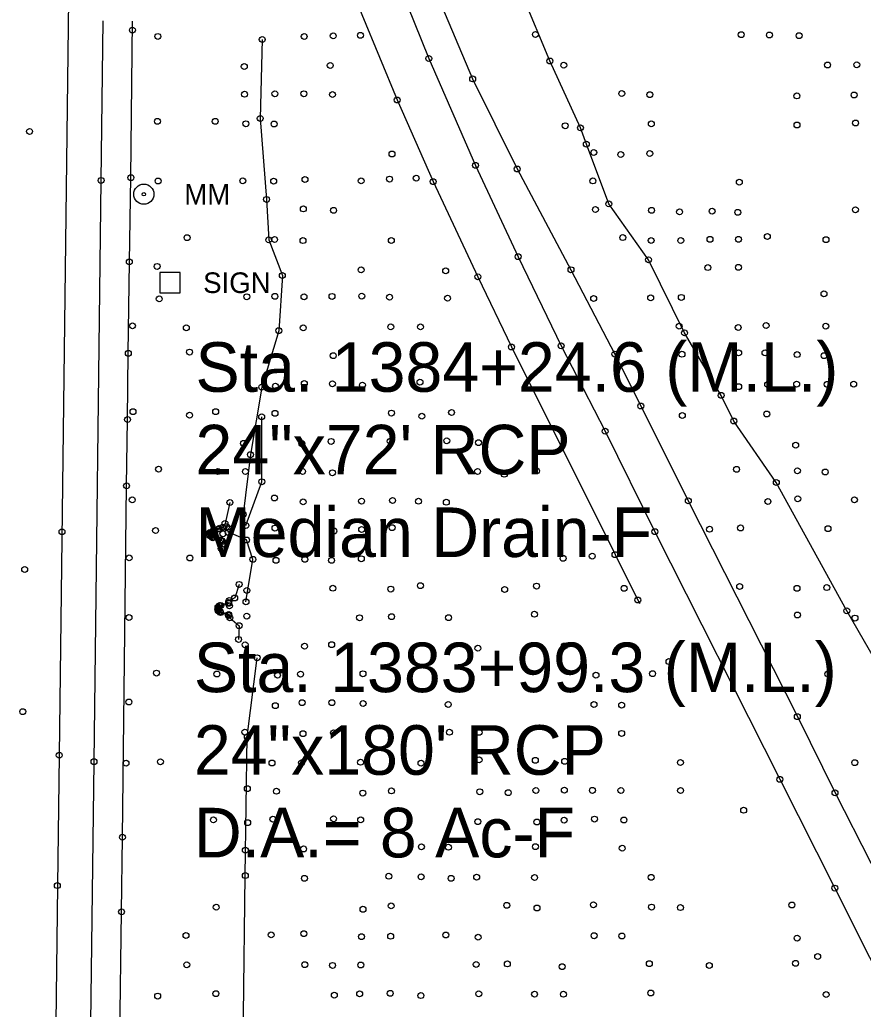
# Model space of a CAD drawing. Extents: x 20503438 to 20508873, y 7964251 to 7984667.
# Drawn here: x 20506709.7 to 20506995.6, y 7971063.7 to 7971399 of the extents above; entities that cross this region are included whole.
import ezdxf

# ---------------------------------------------------------------- set-up
doc = ezdxf.new("R2010")
doc.units = 0
for name, color, linetype in [('SurBreakLine', 7, 'Continuous'), ('SurConcreteSlab', 7, 'Continuous'), ('SurDrainageArrowDown', 7, 'Continuous'), ('SurDrainageArrowUp', 7, 'Continuous'), ('SurEdgeRoadPaved', 7, 'Continuous'), ('SurEdgeShoulderPaved', 7, 'Continuous'), ('SurPointsNonDTM', 7, 'Continuous'), ('SurRoadPoints', 7, 'Continuous'), ('SurSurveyPoints', 7, 'Continuous'), ('SurTxtDrainage', 7, 'Continuous')]:
    doc.layers.add(name, color=color, linetype=linetype)

msp = doc.modelspace()

# ---------------------------------------------------------------- linework, layer by layer
at = {"layer": 'SurBreakLine'}
for points in [[(20506748.06, 7973121.35), (20506742.68, 7972730.78), (20506738.51, 7972374.69), (20506737.86, 7972337.8), (20506736.71, 7972242.37), (20506735.23, 7972125.23), (20506734.95, 7972091.62), (20506733.69, 7971999.07), (20506733.06, 7971941.23), (20506731.39, 7971811.28), (20506730.1, 7971695.4), (20506729.05, 7971627.9), (20506728.3, 7971561.44), (20506726.5, 7971429.38), (20506726.18, 7971406.05), (20506723.05, 7971149.78), (20506722.41, 7971105.59), (20506719.46, 7970853.94), (20506718.67, 7970817.35), (20506718.46, 7970790.57), (20506717.85, 7970756.37), (20506717.5, 7970726.21), (20506716.72, 7970686.1), (20506716.2, 7970609.97)], [(20506780.89, 7971235.43), (20506779.24, 7971228.33), (20506778.42, 7971227.05), (20506775.45, 7971226.15), (20506774.06, 7971225.2), (20506774.11, 7971224.15), (20506775.06, 7971223.48), (20506778.01, 7971222.5), (20506778.4, 7971222.21), (20506777.97, 7971219.86)], [(20506784.01, 7971207.67), (20506782.52, 7971203.07), (20506780.66, 7971202.2)], [(20506780.57, 7971197.26), (20506780.88, 7971196.35), (20506784, 7971193.68), (20506783.83, 7971189.03)]]:
    msp.add_lwpolyline(points, dxfattribs=at)
at = {"layer": 'SurConcreteSlab'}
msp.add_lwpolyline([(20506833.63, 7971422.4), (20506848.3, 7971385.94), (20506864.15, 7971349.7), (20506878.6, 7971318.75), (20506893.18, 7971288.54), (20506908.07, 7971259.59), (20506924.96, 7971225.54), (20506967.3, 7971141.62), (20506985.94, 7971104.75), (20506997.76, 7971081.32), (20507017.18, 7971042.95), (20507056.79, 7970964.03), (20507084.68, 7970908.59), (20507110.53, 7970856.92), (20507136.29, 7970805.35), (20507160.76, 7970756.88), (20507196.93, 7970685.17), (20507205.99, 7970667.01), (20507228.8, 7970620.83), (20507263.82, 7970554.5)], dxfattribs=at)
for points in [[(20506778.13, 7971222.53), (20506775.12, 7971223.72), (20506774.58, 7971224.33), (20506774.56, 7971225.28), (20506775.09, 7971225.84), (20506777.19, 7971226.63), (20506778.42, 7971226.96), (20506777.25, 7971226.37), (20506775.14, 7971225.72), (20506774.71, 7971224.99), (20506774.85, 7971224.22), (20506775.53, 7971223.68), (20506777.73, 7971222.73)], [(20506780.47, 7971201.27), (20506777.83, 7971200.52), (20506776.99, 7971199.91), (20506776.95, 7971199.07), (20506777.53, 7971198.46), (20506780.49, 7971197.48), (20506780.43, 7971197.16), (20506777.73, 7971198.12), (20506776.9, 7971198.75), (20506776.8, 7971199.27), (20506776.86, 7971199.89), (20506777.41, 7971200.52), (20506780.47, 7971201.58)]]:
    msp.add_lwpolyline(points, close=True, dxfattribs=at)
at = {"layer": 'SurDrainageArrowDown'}
for points in [[(20507224.7, 7970759.18), (20507204.45, 7970804.1), (20507184.9, 7970841.74), (20507169.23, 7970884.93), (20507146.3, 7970924.33), (20507137.63, 7970936.09), (20507135.68, 7970938.54), (20507132.89, 7970943.61), (20507112.81, 7970984), (20507088.76, 7971026.9), (20507065.73, 7971065.56), (20507040.06, 7971109.35), (20507016.49, 7971152.89), (20506989.99, 7971198.73), (20506966.12, 7971242.22), (20506951.68, 7971263.05), (20506947.42, 7971271.75), (20506935.02, 7971292.93), (20506922.81, 7971317.7), (20506909.33, 7971336.65), (20506901.73, 7971356.91), (20506899.73, 7971362.43), (20506889.38, 7971385.08), (20506880.22, 7971407.2)], [(20506791.87, 7971392.37), (20506791.18, 7971365.61), (20506793.32, 7971338.17), (20506794.07, 7971324.45), (20506798.67, 7971312.37), (20506797.47, 7971293.67), (20506791.69, 7971274.55), (20506787.85, 7971251.66), (20506785.4, 7971231.45)], [(20506758.23, 7970612.66), (20506759.96, 7970618.07), (20506766.03, 7970640.28), (20506769.58, 7970650.69), (20506772.91, 7970661.98), (20506773.11, 7970678.32), (20506770.25, 7970703.37), (20506769.67, 7970724.66), (20506772.21, 7970747.11), (20506774.83, 7970769.77), (20506774.2, 7970791.54), (20506775.89, 7970837.25), (20506778.93, 7970889.1), (20506783.31, 7970939.45), (20506783.6, 7970964.79), (20506784.75, 7971014.54), (20506785.47, 7971061.82), (20506786.12, 7971108.98), (20506786.8, 7971156.01), (20506790.11, 7971182.82)]]:
    msp.add_lwpolyline(points, dxfattribs=at)
at = {"layer": 'SurDrainageArrowUp'}
for points in [[(20506786.33, 7971227.62), (20506791.69, 7971242.47), (20506791.67, 7971264.48)], [(20506786.34, 7971201.77), (20506788.69, 7971216.16), (20506786.54, 7971222.74), (20506780.31, 7971225.34)]]:
    msp.add_lwpolyline(points, dxfattribs=at)
at = {"layer": 'SurEdgeRoadPaved'}
for points in [[(20506743.39, 7971800.54), (20506747.79, 7971744.03), (20506751.01, 7971706.87), (20506755, 7971665.38), (20506760.15, 7971636.1), (20506765.16, 7971607.46), (20506771.8, 7971576.17), (20506779.74, 7971543.31), (20506787.73, 7971513.32), (20506796.06, 7971484.28), (20506807.04, 7971451.34), (20506815.03, 7971428.73), (20506825.58, 7971400.86), (20506837.6, 7971371.87), (20506849.8, 7971344.18), (20506864.95, 7971311.94), (20506876.32, 7971288.15), (20506911.44, 7971217.76), (20506919.79, 7971201.17)], [(20506851.33, 7971406.99), (20506863.18, 7971379), (20506878.28, 7971348.48), (20506896.51, 7971314.33), (20506911.4, 7971285.72), (20506920.16, 7971268.15), (20506936.29, 7971235.99), (20506973.25, 7971162.85), (20506986.02, 7971137.03), (20506998.15, 7971113.28), (20507008.91, 7971092.3), (20507021.67, 7971066.98), (20507054.15, 7971002), (20507084.27, 7970942.48), (20507118.86, 7970873.87), (20507143.37, 7970824.92), (20507173.68, 7970764.24), (20507214.03, 7970684.3), (20507241.61, 7970629.82), (20507252.24, 7970614.59), (20507261.23, 7970604), (20507267.87, 7970598.31), (20507278.37, 7970591.06), (20507287.18, 7970585.98)], [(20506728.28, 7970614.49), (20506729.78, 7970744.63), (20506731.29, 7970864.38), (20506734.84, 7971147.58), (20506737.24, 7971344.61), (20506737.94, 7971398.74)]]:
    msp.add_lwpolyline(points, dxfattribs=at)
at = {"layer": 'SurEdgeShoulderPaved'}
msp.add_lwpolyline([(20506738.37, 7970630.83), (20506738.67, 7970664.94), (20506740.63, 7970809.56), (20506741.32, 7970878.14), (20506742.07, 7970919.76), (20506742.54, 7970949.49), (20506742.91, 7970990.73), (20506743.22, 7971026.05), (20506743.58, 7971054.27), (20506744.17, 7971096.69), (20506744.47, 7971121.99), (20506745.87, 7971241.09), (20506746.19, 7971263.55), (20506746.45, 7971286), (20506746.82, 7971317), (20506747.35, 7971345.54), (20506747.87, 7971398.62)], dxfattribs=at)
at = {"layer": 'SurPointsNonDTM'}
msp.add_circle((20506723.97, 7971225.51), 1, dxfattribs=at)
at = {"layer": 'SurRoadPoints'}
msp.add_lwpolyline([(20506760.62, 7971306.5), (20506760.62, 7971306.5), (20506764.05, 7971306.5), (20506764.05, 7971313.36), (20506757.19, 7971313.36), (20506757.19, 7971306.5), (20506760.62, 7971306.5)], dxfattribs=at)
for radius in [3.43, 0.571]:
    msp.add_circle((20506751.72, 7971339.93), radius, dxfattribs=at)
at = {"layer": 'SurSurveyPoints'}
for centre in [(20506747.84, 7971395.54), (20506756.47, 7971393.42), (20506791.87, 7971392.37), (20506806.08, 7971393.38), (20506815.91, 7971393.6), (20506825.14, 7971393.78), (20506884.45, 7971394.08), (20506954.23, 7971393.99), (20506963.77, 7971393.89), (20506973.84, 7971393.66), (20506848.3, 7971385.94), (20506785.77, 7971383.19), (20506814.92, 7971383.56), (20506889.38, 7971385.08), (20506894.08, 7971383.66), (20506983.48, 7971383.73), (20506993.39, 7971383.8), (20506863.18, 7971379), (20506785.86, 7971373.8), (20506796.14, 7971373.96), (20506805.98, 7971373.98), (20506815.67, 7971373.71), (20506913.74, 7971374.05), (20506923.24, 7971373.67), (20506973.11, 7971373.24), (20506992.47, 7971373.55), (20506837.6, 7971371.87), (20506791.18, 7971365.61), (20506756.34, 7971364.63), (20506775.91, 7971364.62), (20506786.31, 7971363.81), (20506795.87, 7971363.73), (20506894.55, 7971363.14), (20506899.73, 7971362.43), (20506923.75, 7971363.77), (20506973.13, 7971363.38), (20506992.98, 7971364.05), (20506712.99, 7971361.19), (20506901.73, 7971356.91), (20506835.83, 7971353.57), (20506904.25, 7971354.06), (20506913.4, 7971353.38), (20506923.22, 7971353.7), (20506864.15, 7971349.7), (20506878.28, 7971348.48), (20506747.35, 7971345.54), (20506844.05, 7971345.37), (20506737.24, 7971344.61), (20506756.55, 7971344.41), (20506785.26, 7971344.46), (20506795.72, 7971344.35), (20506806.35, 7971344.92), (20506825.39, 7971344.44), (20506835.01, 7971345.06), (20506849.8, 7971344.18), (20506903.95, 7971344.43), (20506953.57, 7971343.99), (20506793.32, 7971338.17), (20506909.33, 7971336.65), (20506805.8, 7971334.94), (20506816.05, 7971334.46), (20506904.8, 7971334.73), (20506923.83, 7971334.45), (20506933.31, 7971333.93), (20506944.35, 7971334.18), (20506953.06, 7971333.77), (20506992.93, 7971334.65), (20506766.37, 7971325.21), (20506914.07, 7971325.22), (20506963.08, 7971325.59), (20506794.07, 7971324.45), (20506796.03, 7971324.56), (20506805.67, 7971324.2), (20506835.61, 7971324.24), (20506923.7, 7971324.24), (20506933.73, 7971324.23), (20506943.64, 7971324.64), (20506953.3, 7971324.63), (20506982.96, 7971324.52), (20506878.6, 7971318.75), (20506746.82, 7971317), (20506756.23, 7971315.46), (20506922.81, 7971317.7), (20506942.9, 7971315.06), (20506953.29, 7971315.16), (20506798.67, 7971312.37), (20506825.36, 7971314.29), (20506854.04, 7971313.96), (20506864.95, 7971311.94), (20506896.51, 7971314.33), (20506786.61, 7971305.18), (20506796.15, 7971305.3), (20506806.02, 7971305.17), (20506815.52, 7971305.29), (20506825.6, 7971305.39), (20506835.02, 7971305.02), (20506933.91, 7971304.95), (20506982.27, 7971306.18), (20506756.93, 7971304.45), (20506854.68, 7971304.67), (20506904.2, 7971304.58), (20506923.53, 7971304.79), (20506747.88, 7971295.32), (20506835.44, 7971294.97), (20506845.5, 7971294.95), (20506933.19, 7971295.19), (20506962.64, 7971295.42), (20506982.89, 7971295.2), (20506766.11, 7971294.66), (20506797.47, 7971293.67), (20506805.76, 7971294.63), (20506935.02, 7971292.93), (20506953.21, 7971294.75), (20506876.32, 7971288.15), (20506893.18, 7971288.54), (20506746.45, 7971286), (20506767.21, 7971286.42), (20506786.85, 7971284.92), (20506815.93, 7971285.2), (20506911.4, 7971285.72), (20506934.13, 7971285.68), (20506953.35, 7971286.15), (20506962.3, 7971286.18), (20506973.19, 7971285.57), (20506982.33, 7971285.2), (20506796.34, 7971274.87), (20506806.11, 7971275.76), (20506815.64, 7971275.67), (20506825.81, 7971275.22), (20506845.32, 7971276.23), (20506953.36, 7971274.71), (20506963.17, 7971275.41), (20506973.01, 7971275.56), (20506983.36, 7971275.5), (20506992.34, 7971275.57), (20506791.69, 7971274.55), (20506947.42, 7971271.75), (20506920.16, 7971268.15), (20506748.06, 7971266.22), (20506767.23, 7971265.01), (20506776.08, 7971266.23), (20506796.17, 7971265.65), (20506835.66, 7971265.75), (20506845.96, 7971264.68), (20506856.03, 7971265.94), (20506934.25, 7971264.93), (20506962.89, 7971265.42), (20506746.19, 7971263.55), (20506791.67, 7971264.48), (20506951.68, 7971263.05), (20506908.07, 7971259.59), (20506785.5, 7971255.48), (20506805.31, 7971255.37), (20506815.19, 7971256.14), (20506835.23, 7971256.21), (20506854.42, 7971256.36), (20506865.17, 7971255.7), (20506972.68, 7971254.86), (20506787.85, 7971251.66), (20506756.71, 7971246.73), (20506776.82, 7971245.95), (20506786.17, 7971245.93), (20506805.53, 7971245.95), (20506815.66, 7971245.53), (20506864.84, 7971245.97), (20506873.92, 7971245.01), (20506884.84, 7971246.14), (20506952.64, 7971246.67), (20506973.29, 7971246.19), (20506982.71, 7971245.77), (20506791.69, 7971242.47), (20506966.12, 7971242.22), (20506745.87, 7971241.09), (20506747.8, 7971236.32), (20506780.89, 7971235.43), (20506795.99, 7971236.95), (20506805.73, 7971235.65), (20506825.52, 7971235.91), (20506836.05, 7971236.13), (20506844.82, 7971235.86), (20506854.25, 7971235.52), (20506936.29, 7971235.99), (20506963.28, 7971235.77), (20506973.38, 7971236.69), (20506992.59, 7971236.34), (20506785.4, 7971231.45), (20506779.24, 7971228.33), (20506755.7, 7971225.93), (20506774.06, 7971225.2), (20506774.56, 7971225.28), (20506774.71, 7971224.99), (20506775.09, 7971225.84), (20506775.14, 7971225.72), (20506775.45, 7971226.15), (20506777.19, 7971226.63), (20506777.25, 7971226.37), (20506778.42, 7971227.05), (20506778.42, 7971226.96), (20506778.51, 7971224.82), (20506779.78, 7971227.25), (20506780.31, 7971225.34), (20506780.67, 7971226.49), (20506786.33, 7971227.62), (20506796.17, 7971226.77), (20506816.14, 7971225.77), (20506825.55, 7971226.29), (20506835.89, 7971226.89), (20506924.96, 7971225.54), (20506943.48, 7971226.37), (20506954, 7971226.81), (20506983.65, 7971226.58), (20506774.11, 7971224.15), (20506774.58, 7971224.33), (20506774.85, 7971224.22), (20506775.06, 7971223.48), (20506775.12, 7971223.72), (20506775.53, 7971223.68), (20506777.73, 7971222.73), (20506778.01, 7971222.5), (20506778.13, 7971222.53), (20506778.4, 7971222.21), (20506786.54, 7971222.74), (20506777.97, 7971219.86), (20506911.44, 7971217.76), (20506746.75, 7971216.66), (20506767.33, 7971216.63), (20506788.69, 7971216.16), (20506796.52, 7971215.84), (20506806.29, 7971216.16), (20506815.36, 7971215.82), (20506825.44, 7971216.37), (20506893.83, 7971216.5), (20506903.73, 7971217.27), (20506711.34, 7971212.75), (20506784.01, 7971207.67), (20506786.63, 7971205.62), (20506815.79, 7971206.37), (20506835.43, 7971206.09), (20506845.47, 7971207.24), (20506874.02, 7971205.97), (20506884.84, 7971207.11), (20506914.52, 7971206.36), (20506953.68, 7971206.98), (20506973.14, 7971206.35), (20506983.23, 7971206.59), (20506780.47, 7971201.58), (20506780.47, 7971201.27), (20506780.66, 7971202.2), (20506782.52, 7971203.07), (20506786.34, 7971201.77), (20506919.18, 7971202.38), (20506776.8, 7971199.27), (20506776.86, 7971199.89), (20506776.9, 7971198.75), (20506776.95, 7971199.07), (20506776.99, 7971199.91), (20506777.41, 7971200.52), (20506777.53, 7971198.46), (20506777.73, 7971198.12), (20506777.83, 7971200.52), (20506780.73, 7971200.39), (20506884.14, 7971197.56), (20506989.99, 7971198.73), (20506746.68, 7971196.44), (20506780.43, 7971197.16), (20506780.49, 7971197.48), (20506780.57, 7971197.26), (20506780.88, 7971196.35), (20506786.61, 7971196.92), (20506824.84, 7971196.38), (20506835.68, 7971196.75), (20506855.02, 7971196.39), (20506973.29, 7971197.29), (20506992.78, 7971196.27), (20506784, 7971193.68), (20506783.83, 7971189.03), (20506786.05, 7971187.21), (20506806.2, 7971186.73), (20506815.4, 7971187.25), (20506864.95, 7971186.05), (20506894.26, 7971186.79), (20506790.11, 7971182.82), (20506929.74, 7971181.51), (20506756.01, 7971177.62), (20506924.18, 7971177.43), (20506776.5, 7971177.31), (20506797.04, 7971176.91), (20506804.86, 7971177.26), (20506826.01, 7971177.4), (20506904.99, 7971176.9), (20506983.58, 7971177.33), (20506746.67, 7971167.83), (20506805.37, 7971167.58), (20506815.46, 7971167.58), (20506710.67, 7971164.55), (20506796.29, 7971166.56), (20506826.06, 7971167.31), (20506854.92, 7971166.99), (20506904.31, 7971166.95), (20506913.69, 7971166.75), (20506973.25, 7971162.85), (20506785.99, 7971157.6), (20506816.04, 7971157.35), (20506855.31, 7971157.56), (20506865.37, 7971157.55), (20506786.8, 7971156.01), (20506805.69, 7971157.09), (20506913.68, 7971157.17), (20506723.05, 7971149.78), (20506734.84, 7971147.58), (20506757.34, 7971147.55), (20506825.2, 7971147.39), (20506865.36, 7971148.19), (20506884.44, 7971148.06), (20506894.37, 7971147.69), (20506933.6, 7971147.3), (20506992.7, 7971147.27), (20506745.68, 7971147.07), (20506795.18, 7971147.15), (20506805.19, 7971147.21), (20506845.68, 7971147.06), (20506967.3, 7971141.62), (20506786.8, 7971138.43), (20506796.66, 7971137.56), (20506835.65, 7971137.68), (20506865.58, 7971137.4), (20506884.61, 7971137.83), (20506894.27, 7971137.96), (20506903.77, 7971137.86), (20506913.43, 7971137.84), (20506933.67, 7971137.81), (20506825.94, 7971136.95), (20506875.26, 7971137.07), (20506986.02, 7971137.03), (20506955.05, 7971131.12), (20506775.31, 7971127.87), (20506795.46, 7971128.11), (20506816.04, 7971128.24), (20506825.23, 7971127.87), (20506864.94, 7971127.27), (20506884.96, 7971127.15), (20506894.19, 7971127.77), (20506904.49, 7971128.14), (20506914.46, 7971127.83), (20506786.93, 7971126.93), (20506744.47, 7971121.99), (20506786.14, 7971117.58), (20506805.85, 7971118.01), (20506845.81, 7971118.73), (20506854.98, 7971118.58), (20506884.46, 7971118.78), (20506913.89, 7971118.26), (20506786.12, 7971108.98), (20506806.17, 7971108.05), (20506834.76, 7971108.75), (20506845.7, 7971108.56), (20506855.89, 7971108.04), (20506864.54, 7971108.44), (20506884.16, 7971108.31), (20506923.7, 7971108.4), (20506722.41, 7971105.59), (20506985.94, 7971104.75), (20506776.26, 7971098.26), (20506826.01, 7971097.56), (20506835.56, 7971098.71), (20506874.76, 7971098.89), (20506885.01, 7971098), (20506904.11, 7971099.08), (20506923.84, 7971098.31), (20506933.61, 7971098.13), (20506971.4, 7971099.02), (20506744.17, 7971096.69), (20506766.01, 7971088.67), (20506794.88, 7971088.89), (20506805.96, 7971089.29), (20506825.5, 7971088.28), (20506835.38, 7971088.42), (20506854.09, 7971088.85), (20506865.05, 7971088.1), (20506904.34, 7971088.6), (20506913.79, 7971088.49), (20506973.15, 7971087.78), (20506980.14, 7971081.53), (20506766.28, 7971078.75), (20506806.28, 7971078.78), (20506815.7, 7971078.54), (20506825.26, 7971078.69), (20506864.37, 7971078.86), (20506874.95, 7971079.04), (20506893.53, 7971078.11), (20506923.08, 7971079.12), (20506943.4, 7971078.51), (20506972.64, 7971079.25), (20506756.42, 7971068.15), (20506776.14, 7971068.96), (20506816.29, 7971068.43), (20506824.87, 7971068.9), (20506835.24, 7971069.06), (20506845.65, 7971068.31), (20506865.24, 7971068.91), (20506884.17, 7971068.79), (20506893.94, 7971068.76), (20506923.57, 7971069.19), (20506983.02, 7971068.66)]:
    msp.add_circle(centre, 1, dxfattribs=at)

# ---------------------------------------------------------------- texts
at = {"layer": 'SurRoadPoints'}
for s, p in [('MM', (20506765.43, 7971336.43)), ('SIGN', (20506771.83, 7971306.43))]:
    msp.add_text(s, height=6.995, rotation=360, dxfattribs=at).set_placement(p)
at = {"layer": 'SurTxtDrainage'}
for s, p in [('Sta. 1384+24.6 (M.L.)', (20506769.22, 7971272.96)), ('24"x72\' RCP', (20506769.22, 7971244.96)), ('Median Drain-F', (20506769.22, 7971216.96)), ('Sta. 1383+99.3 (M.L.)', (20506768.68, 7971171.15)), ('24"x180\' RCP', (20506768.68, 7971143.15)), ('D.A.= 8 Ac-F', (20506768.68, 7971115.15))]:
    msp.add_text(s, height=16.8, dxfattribs=at).set_placement(p)

doc.saveas('drawing.dxf')
